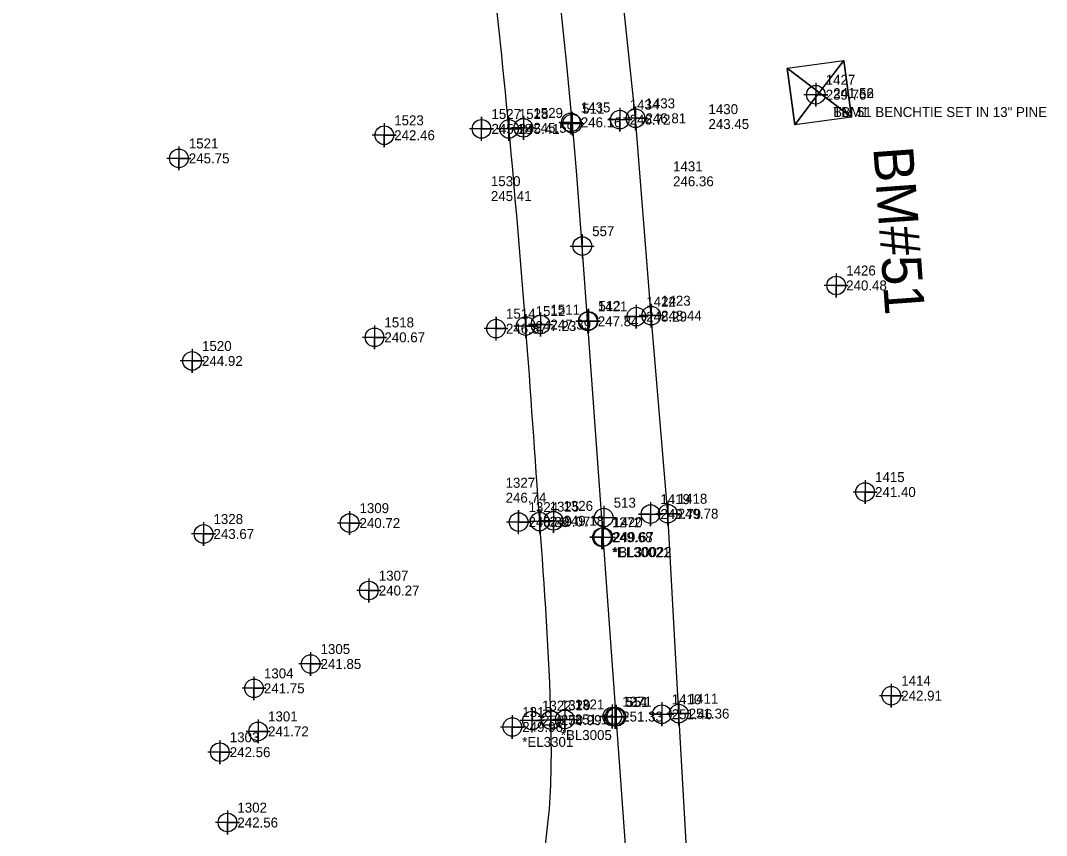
# Model space of a CAD drawing. Extents: x 2130621 to 2131998, y 642516 to 644503.
# Drawn here: x 2131091.5 to 2131349.5, y 643288.8 to 643493.6 of the extents above; entities that cross this region are included whole.
import ezdxf

# ---------------------------------------------------------------- set-up
doc = ezdxf.new("R2010")
doc.units = 0
for name, color, linetype in [('Cogo Default Point CELL', 7, 'Continuous'), ('COGO Default Point Number', 7, 'Continuous'), ('CTL Vertical Benchmark CELL', 7, 'Continuous'), ('CTL Vertical Benchmark Cogo Comment', 7, 'Continuous'), ('CTL Vertical Benchmark Cogo Elevation', 7, 'Continuous'), ('CTL Vertical Benchmark Text', 7, 'Continuous'), ('Exist Guardrail Cogo Comment', 7, 'Continuous'), ('Exist Guardrail Cogo Elevation', 7, 'Continuous'), ('Exist Guardrail Cogo Number', 7, 'Continuous'), ('Exist Guardrail Cogo Point CELL', 7, 'Continuous'), ('Exist Other Culture Fence Line Cogo Elevation', 7, 'Continuous'), ('Exist Other Culture Fence Line Cogo Number', 7, 'Continuous'), ('Exist Other Culture Fence Line Cogo Point CELL', 7, 'Continuous'), ('Exist Other Culture Sign Cogo Elevation', 7, 'Continuous'), ('Exist Other Culture Sign Cogo Number', 7, 'Continuous'), ('Exist Roads EOP', 7, 'Continuous'), ('Exist Roads EOP Cogo Elevation', 7, 'Continuous'), ('Exist Roads EOP Cogo Number', 7, 'Continuous'), ('Exist Roads EOP Cogo Point CELL', 7, 'Continuous'), ('Exist Roads EOT Cogo Comment', 7, 'Continuous'), ('Exist Roads EOT Cogo Elevation', 7, 'Continuous'), ('Exist Roads EOT Cogo Number', 7, 'Continuous'), ('Exist Roads EOT Cogo Point CELL', 7, 'Continuous'), ('Exist Roads Soil Cogo Comment', 7, 'Continuous'), ('Exist Roads Soil Cogo Elevation', 7, 'Continuous'), ('Exist Roads Soil Cogo Number', 7, 'Continuous'), ('Exist Roads Soil Cogo Point CELL', 7, 'Continuous'), ('Exist Vegetation Woods Line Cogo Elevation', 7, 'Continuous'), ('Exist Vegetation Woods Line Cogo Number', 7, 'Continuous'), ('Exist Vegetation Woods Line Cogo Point CELL', 7, 'Continuous'), ('Prop Horizontal Alignment', 7, 'Continuous')]:
    doc.layers.add(name, color=color, linetype=linetype)

msp = doc.modelspace()

# ---------------------------------------------------------------- linework, layer by layer
at = {"layer": 'Cogo Default Point CELL'}
for points in [[(2131230.23, 643470.69), (2131230.23, 643467.69)], [(2131227.23, 643467.69), (2131230.23, 643467.69)], [(2131230.23, 643467.69), (2131233.23, 643467.69)], [(2131230.23, 643467.69), (2131230.23, 643464.69)], [(2131232.75, 643439.91), (2131232.75, 643436.91)], [(2131232.75, 643439.91), (2131232.75, 643436.91)], [(2131229.75, 643436.91), (2131232.75, 643436.91)], [(2131229.75, 643436.91), (2131232.75, 643436.91)], [(2131232.75, 643436.91), (2131235.75, 643436.91)], [(2131232.75, 643436.91), (2131232.75, 643433.91)], [(2131232.75, 643436.91), (2131235.75, 643436.91)], [(2131232.75, 643436.91), (2131232.75, 643433.91)], [(2131234.31, 643421.12), (2131234.31, 643418.12)], [(2131231.31, 643418.12), (2131234.31, 643418.12)], [(2131234.31, 643418.12), (2131237.31, 643418.12)], [(2131234.31, 643418.12), (2131234.31, 643415.12)], [(2131238.16, 643371.66), (2131238.16, 643368.66)], [(2131235.16, 643368.66), (2131238.16, 643368.66)], [(2131238.16, 643368.66), (2131241.16, 643368.66)], [(2131238.16, 643368.66), (2131238.16, 643365.66)], [(2131240.95, 643321.6), (2131240.95, 643318.6)], [(2131241.32, 643321.6), (2131241.32, 643318.6)], [(2131237.95, 643318.6), (2131240.95, 643318.6)], [(2131238.32, 643318.6), (2131241.32, 643318.6)], [(2131240.95, 643318.6), (2131243.95, 643318.6)], [(2131240.95, 643318.6), (2131240.95, 643315.6)], [(2131241.32, 643318.6), (2131244.32, 643318.6)], [(2131241.32, 643318.6), (2131241.32, 643315.6)]]:
    msp.add_lwpolyline(points, dxfattribs=at)
for centre in [(2131230.23, 643467.69), (2131232.75, 643436.91), (2131232.75, 643436.91), (2131234.31, 643418.12), (2131238.16, 643368.66), (2131240.95, 643318.6), (2131241.32, 643318.6)]:
    msp.add_circle(centre, 2.34, dxfattribs=at)
at = {"layer": 'CTL Vertical Benchmark CELL'}
msp.add_line((2131292.37, 643475.49), (2131292.37, 643475.49), dxfattribs=at)
msp.add_lwpolyline([(2131298.52, 643483.58), (2131300.44, 643469.34), (2131286.19, 643467.41), (2131284.27, 643481.66)], close=True, dxfattribs=at)
for points in [[(2131300.44, 643469.34), (2131284.27, 643481.66), (2131292.35, 643475.5), (2131286.19, 643467.41), (2131298.52, 643483.58)], [(2131292.35, 643475.5), (2131300.44, 643469.34), (2131298.52, 643483.58), (2131292.35, 643475.5)], [(2131292.35, 643475.5), (2131284.27, 643481.66), (2131286.19, 643467.41), (2131292.35, 643475.5)]]:
    msp.add_lwpolyline(points, dxfattribs=at)
at = {"layer": 'Exist Guardrail Cogo Point CELL'}
msp.add_lwpolyline([(2131215.17, 643319.03), (2131215.17, 643313.03), (2131215.17, 643316.03), (2131218.17, 643316.03), (2131212.17, 643316.03)], dxfattribs=at)
msp.add_circle((2131215.17, 643316.03), 2.34, dxfattribs=at)
at = {"layer": 'Exist Other Culture Fence Line Cogo Point CELL'}
for points in [[(2131131.35, 643461.95), (2131131.35, 643455.95), (2131131.35, 643458.95), (2131134.35, 643458.95), (2131128.35, 643458.95)], [(2131134.67, 643411.04), (2131134.67, 643405.04), (2131134.67, 643408.04), (2131137.67, 643408.04), (2131131.67, 643408.04)], [(2131137.55, 643367.55), (2131137.55, 643361.55), (2131137.55, 643364.55), (2131140.55, 643364.55), (2131134.55, 643364.55)], [(2131141.64, 643312.7), (2131141.64, 643306.7), (2131141.64, 643309.7), (2131144.64, 643309.7), (2131138.64, 643309.7)], [(2131143.56, 643295.02), (2131143.56, 643289.02), (2131143.56, 643292.02), (2131146.56, 643292.02), (2131140.56, 643292.02)]]:
    msp.add_lwpolyline(points, dxfattribs=at)
for centre in [(2131131.35, 643458.95), (2131134.67, 643408.04), (2131137.55, 643364.55), (2131141.64, 643309.7), (2131143.56, 643292.02)]:
    msp.add_circle(centre, 2.34, dxfattribs=at)
at = {"layer": 'Exist Roads EOP'}
msp.add_lwpolyline([(2131264.27, 643222.56), (2131259.88, 643269.33), (2131257.02, 643319.4), (2131254.26, 643369.65), (2131250.08, 643419.42), (2131246.15, 643469.03), (2131240.84, 643519.13), (2131234.37, 643568.56), (2131226.33, 643620.18), (2131217.03, 643668.71), (2131205.62, 643717.61), (2131192.06, 643767.26), (2131177.97, 643815.09), (2131162.29, 643862.93), (2131145.36, 643910.85), (2131126.91, 643957.29), (2131112.37, 643996.12)], dxfattribs=at)
msp.add_spline([(2131166.25, 643216.7), (2131171.81, 643218.72), (2131182.37, 643223.97), (2131191.81, 643231.15), (2131200.5, 643239.7), (2131208.81, 643249.07), (2131216.07, 643259), (2131218.72, 643264.35), (2131220.54, 643270.1), (2131222.84, 643282.01), (2131224.36, 643293.92), (2131224.88, 643317.79), (2131222.06, 643367.67), (2131218.54, 643416.81), (2131214.32, 643466.35), (2131209.17, 643515.67), (2131202.79, 643565.15), (2131195.05, 643613.99), (2131186.4, 643662.48), (2131176.01, 643711.41), (2131164.62, 643759.89), (2131151.87, 643807.85), (2131137.86, 643855.41), (2131122.57, 643902.86), (2131105.96, 643949.49), (2131091.53, 643988.04)], degree=3, dxfattribs=at)
at = {"layer": 'Exist Roads EOP Cogo Point CELL'}
for points in [[(2131246.15, 643472.03), (2131246.15, 643466.03), (2131246.15, 643469.03), (2131249.15, 643469.03), (2131243.15, 643469.03)], [(2131214.32, 643469.35), (2131214.32, 643463.35), (2131214.32, 643466.35), (2131217.32, 643466.35), (2131211.32, 643466.35)], [(2131250.08, 643422.42), (2131250.08, 643416.42), (2131250.08, 643419.42), (2131253.08, 643419.42), (2131247.08, 643419.42)], [(2131218.54, 643419.81), (2131218.54, 643413.81), (2131218.54, 643416.81), (2131221.54, 643416.81), (2131215.54, 643416.81)], [(2131254.26, 643372.65), (2131254.26, 643366.65), (2131254.26, 643369.65), (2131257.26, 643369.65), (2131251.26, 643369.65)], [(2131222.06, 643370.67), (2131222.06, 643364.67), (2131222.06, 643367.67), (2131225.06, 643367.67), (2131219.06, 643367.67)], [(2131224.88, 643320.79), (2131224.88, 643314.79), (2131224.88, 643317.79), (2131227.88, 643317.79), (2131221.88, 643317.79)], [(2131257.02, 643322.4), (2131257.02, 643316.4), (2131257.02, 643319.4), (2131260.02, 643319.4), (2131254.02, 643319.4)]]:
    msp.add_lwpolyline(points, dxfattribs=at)
for centre in [(2131246.15, 643469.03), (2131214.32, 643466.35), (2131250.08, 643419.42), (2131218.54, 643416.81), (2131254.26, 643369.65), (2131222.06, 643367.67), (2131224.88, 643317.79), (2131257.02, 643319.4)]:
    msp.add_circle(centre, 2.34, dxfattribs=at)
at = {"layer": 'Exist Roads EOT Cogo Point CELL'}
for points in [[(2131217.96, 643469.63), (2131217.96, 643463.63), (2131217.96, 643466.63), (2131214.96, 643466.63), (2131220.96, 643466.63)], [(2131229.89, 643471.01), (2131229.89, 643465.01), (2131229.89, 643468.01), (2131226.89, 643468.01), (2131232.89, 643468.01)], [(2131242.19, 643471.69), (2131242.19, 643465.69), (2131242.19, 643468.69), (2131239.19, 643468.69), (2131245.19, 643468.69)], [(2131234.16, 643421), (2131234.16, 643415), (2131234.16, 643418), (2131231.16, 643418), (2131237.16, 643418)], [(2131246.35, 643422.18), (2131246.35, 643416.18), (2131246.35, 643419.18), (2131243.35, 643419.18), (2131249.35, 643419.18)], [(2131222.25, 643420.19), (2131222.25, 643414.19), (2131222.25, 643417.19), (2131219.25, 643417.19), (2131225.25, 643417.19)], [(2131249.91, 643372.55), (2131249.91, 643366.55), (2131249.91, 643369.55), (2131246.91, 643369.55), (2131252.91, 643369.55)], [(2131225.53, 643370.86), (2131225.53, 643364.86), (2131225.53, 643367.86), (2131222.53, 643367.86), (2131228.53, 643367.86)], [(2131237.7, 643366.71), (2131237.7, 643360.71), (2131237.7, 643363.71), (2131234.7, 643363.71), (2131240.7, 643363.71)], [(2131238.02, 643366.77), (2131238.02, 643360.77), (2131238.02, 643363.77), (2131235.02, 643363.77), (2131241.02, 643363.77)], [(2131228.38, 643320.94), (2131228.38, 643314.94), (2131228.38, 643317.94), (2131225.38, 643317.94), (2131231.38, 643317.94)], [(2131240.3, 643321.66), (2131240.3, 643315.66), (2131240.3, 643318.66), (2131237.3, 643318.66), (2131243.3, 643318.66)], [(2131252.75, 643322.24), (2131252.75, 643316.24), (2131252.75, 643319.24), (2131249.75, 643319.24), (2131255.75, 643319.24)]]:
    msp.add_lwpolyline(points, dxfattribs=at)
for centre in [(2131229.89, 643468.01), (2131242.19, 643468.69), (2131217.96, 643466.63), (2131246.35, 643419.18), (2131222.25, 643417.19), (2131234.16, 643418), (2131249.91, 643369.55), (2131225.53, 643367.86), (2131237.7, 643363.71), (2131238.02, 643363.77), (2131228.38, 643317.94), (2131240.3, 643318.66), (2131252.75, 643319.24)]:
    msp.add_circle(centre, 2.34, dxfattribs=at)
at = {"layer": 'Exist Roads Soil Cogo Point CELL'}
for points in [[(2131207.43, 643463.36), (2131207.43, 643469.36), (2131207.43, 643466.36), (2131210.43, 643466.36), (2131204.43, 643466.36)], [(2131211.08, 643413.16), (2131211.08, 643419.16), (2131211.08, 643416.16), (2131214.08, 643416.16), (2131208.08, 643416.16)], [(2131216.75, 643364.54), (2131216.75, 643370.54), (2131216.75, 643367.54), (2131219.75, 643367.54), (2131213.75, 643367.54)], [(2131220.14, 643314.65), (2131220.14, 643320.65), (2131220.14, 643317.65), (2131223.14, 643317.65), (2131217.14, 643317.65)], [(2131224.87, 643314.75), (2131224.87, 643320.75), (2131224.87, 643317.75), (2131227.87, 643317.75), (2131221.87, 643317.75)]]:
    msp.add_lwpolyline(points, dxfattribs=at)
for centre in [(2131207.43, 643466.36), (2131211.08, 643416.16), (2131216.75, 643367.54), (2131220.14, 643317.65), (2131224.87, 643317.75)]:
    msp.add_circle(centre, 2.34, dxfattribs=at)
at = {"layer": 'Exist Vegetation Woods Line Cogo Point CELL'}
for points in [[(2131291.47, 643477.95), (2131291.47, 643471.95), (2131291.47, 643474.95), (2131294.47, 643474.95), (2131288.47, 643474.95)], [(2131182.98, 643467.77), (2131182.98, 643461.77), (2131182.98, 643464.77), (2131185.98, 643464.77), (2131179.98, 643464.77)], [(2131296.61, 643430.01), (2131296.61, 643424.01), (2131296.61, 643427.01), (2131299.61, 643427.01), (2131293.61, 643427.01)], [(2131180.52, 643416.97), (2131180.52, 643410.97), (2131180.52, 643413.97), (2131183.52, 643413.97), (2131177.52, 643413.97)], [(2131303.87, 643378.09), (2131303.87, 643372.09), (2131303.87, 643375.09), (2131306.87, 643375.09), (2131300.87, 643375.09)], [(2131174.26, 643370.29), (2131174.26, 643364.29), (2131174.26, 643367.29), (2131177.26, 643367.29), (2131171.26, 643367.29)], [(2131179.11, 643353.33), (2131179.11, 643347.33), (2131179.11, 643350.33), (2131182.11, 643350.33), (2131176.11, 643350.33)], [(2131164.47, 643334.87), (2131164.47, 643328.87), (2131164.47, 643331.87), (2131167.47, 643331.87), (2131161.47, 643331.87)], [(2131150.23, 643328.75), (2131150.23, 643322.75), (2131150.23, 643325.75), (2131153.23, 643325.75), (2131147.23, 643325.75)], [(2131310.45, 643326.9), (2131310.45, 643320.9), (2131310.45, 643323.9), (2131313.45, 643323.9), (2131307.45, 643323.9)], [(2131151.27, 643317.93), (2131151.27, 643311.93), (2131151.27, 643314.93), (2131154.27, 643314.93), (2131148.27, 643314.93)]]:
    msp.add_lwpolyline(points, dxfattribs=at)
for centre in [(2131291.47, 643474.95), (2131182.98, 643464.77), (2131296.61, 643427.01), (2131180.52, 643413.97), (2131303.87, 643375.09), (2131174.26, 643367.29), (2131179.11, 643350.33), (2131164.47, 643331.87), (2131150.23, 643325.75), (2131310.45, 643323.9), (2131151.27, 643314.93)]:
    msp.add_circle(centre, 2.34, dxfattribs=at)
at = {"layer": 'Prop Horizontal Alignment'}
msp.add_line((2131251.47, 643178.51), (2131232.75, 643436.91), dxfattribs=at)
msp.add_arc((2129448.47, 643307.66), 1788.96, 4.14306, 22.49968, dxfattribs=at)

# ---------------------------------------------------------------- texts
at = {"layer": 'COGO Default Point Number'}
for s, p in [('511', (2131232.73, 643470.19)), ('557', (2131235.25, 643439.41)), ('512', (2131236.81, 643420.62)), ('513', (2131240.66, 643371.16)), ('514', (2131243.45, 643321.1)), ('551', (2131243.82, 643321.1))]:
    msp.add_text(s, height=2.5, dxfattribs=at).set_placement(p)
at = {"layer": 'CTL Vertical Benchmark Cogo Comment'}
for s in ['TBM1', 'BM 51 BENCHTIE SET IN 13" PINE']:
    msp.add_text(s, height=2.5, dxfattribs=at).set_placement((2131295.85, 643469.35))
at = {"layer": 'CTL Vertical Benchmark Cogo Elevation'}
for s in ['241.56', '241.52']:
    msp.add_text(s, height=2.5, dxfattribs=at).set_placement((2131295.85, 643474.1))
at = {"layer": 'CTL Vertical Benchmark Text'}
msp.add_text('BM#51   ', height=10, rotation=274.1431, dxfattribs=at).set_placement((2131305.92, 643461.61))
at = {"layer": 'Exist Guardrail Cogo Comment'}
msp.add_text('*EL3301', height=2.5, dxfattribs=at).set_placement((2131217.67, 643311.03))
at = {"layer": 'Exist Guardrail Cogo Elevation'}
msp.add_text('249.96', height=2.5, dxfattribs=at).set_placement((2131217.67, 643314.78))
at = {"layer": 'Exist Guardrail Cogo Number'}
msp.add_text('1318', height=2.5, dxfattribs=at).set_placement((2131217.67, 643318.53))
at = {"layer": 'Exist Other Culture Fence Line Cogo Elevation'}
for s, p in [('245.75', (2131133.85, 643457.7)), ('244.92', (2131137.17, 643406.79)), ('243.67', (2131140.05, 643363.3)), ('242.56', (2131144.14, 643308.45)), ('242.56', (2131146.06, 643290.77))]:
    msp.add_text(s, height=2.5, dxfattribs=at).set_placement(p)
at = {"layer": 'Exist Other Culture Fence Line Cogo Number'}
for s, p in [('1521', (2131133.85, 643461.45)), ('1520', (2131137.17, 643410.54)), ('1328', (2131140.05, 643367.05)), ('1303', (2131144.14, 643312.2)), ('1302', (2131146.06, 643294.52))]:
    msp.add_text(s, height=2.5, dxfattribs=at).set_placement(p)
at = {"layer": 'Exist Other Culture Sign Cogo Elevation'}
for s, p in [('243.45', (2131264.49, 643466.32)), ('246.36', (2131255.59, 643451.94)), ('245.41', (2131209.79, 643448.22)), ('246.74', (2131213.49, 643372.41))]:
    msp.add_text(s, height=2.5, dxfattribs=at).set_placement(p)
at = {"layer": 'Exist Other Culture Sign Cogo Number'}
for s, p in [('1430', (2131264.49, 643470.07)), ('1431', (2131255.59, 643455.69)), ('1530', (2131209.79, 643451.97)), ('1327', (2131213.49, 643376.16))]:
    msp.add_text(s, height=2.5, dxfattribs=at).set_placement(p)
at = {"layer": 'Exist Roads EOP Cogo Elevation'}
for s, p in [('246.81', (2131248.65, 643467.78)), ('245.41', (2131216.82, 643465.1)), ('248.44', (2131252.58, 643418.17)), ('247.23', (2131221.04, 643415.56)), ('249.07', (2131224.56, 643366.42)), ('249.78', (2131256.76, 643368.4)), ('251.36', (2131259.52, 643318.15)), ('250.99', (2131227.38, 643316.54))]:
    msp.add_text(s, height=2.5, dxfattribs=at).set_placement(p)
at = {"layer": 'Exist Roads EOP Cogo Number'}
for s, p in [('1433', (2131248.65, 643471.53)), ('1528', (2131216.82, 643468.85)), ('1423', (2131252.58, 643421.92)), ('1512', (2131221.04, 643419.31)), ('1418', (2131256.76, 643372.15)), ('1325', (2131224.56, 643370.17)), ('1319', (2131227.38, 643320.29)), ('1411', (2131259.52, 643321.9))]:
    msp.add_text(s, height=2.5, dxfattribs=at).set_placement(p)
at = {"layer": 'Exist Roads EOT Cogo Comment'}
for s, p in [('*EL30021', (2131240.2, 643358.71)), ('*BL30022', (2131240.52, 643358.77))]:
    msp.add_text(s, height=2.5, dxfattribs=at).set_placement(p)
at = {"layer": 'Exist Roads EOT Cogo Elevation'}
for s, p in [('246.72', (2131244.69, 643467.44)), ('245.59', (2131220.46, 643465.38)), ('246.16', (2131232.39, 643466.76)), ('247.39', (2131224.75, 643415.94)), ('247.84', (2131236.66, 643416.75)), ('248.29', (2131248.85, 643417.93)), ('249.18', (2131228.03, 643366.61)), ('249.79', (2131252.41, 643368.3)), ('249.68', (2131240.2, 643362.46)), ('249.67', (2131240.52, 643362.52)), ('251.46', (2131255.25, 643317.99)), ('251.11', (2131230.88, 643316.69)), ('251.33', (2131242.8, 643317.41))]:
    msp.add_text(s, height=2.5, dxfattribs=at).set_placement(p)
at = {"layer": 'Exist Roads EOT Cogo Number'}
for s, p in [('1435', (2131232.39, 643470.51)), ('1434', (2131244.69, 643471.19)), ('1529', (2131220.46, 643469.13)), ('1422', (2131248.85, 643421.68)), ('1511', (2131224.75, 643419.69)), ('1421', (2131236.66, 643420.5)), ('1419', (2131252.41, 643372.05)), ('1326', (2131228.03, 643370.36)), ('1272', (2131240.2, 643366.21)), ('1420', (2131240.52, 643366.27)), ('1321', (2131230.88, 643320.44)), ('1271', (2131242.8, 643321.16)), ('1410', (2131255.25, 643321.74))]:
    msp.add_text(s, height=2.5, dxfattribs=at).set_placement(p)
at = {"layer": 'Exist Roads Soil Cogo Comment'}
msp.add_text('*BL3005', height=2.5, dxfattribs=at).set_placement((2131227.37, 643312.75))
at = {"layer": 'Exist Roads Soil Cogo Elevation'}
for s, p in [('245.18', (2131209.93, 643465.11)), ('246.87', (2131213.58, 643414.91)), ('248.89', (2131219.25, 643366.29)), ('250.74', (2131222.64, 643316.4)), ('250.99', (2131227.37, 643316.5))]:
    msp.add_text(s, height=2.5, dxfattribs=at).set_placement(p)
at = {"layer": 'Exist Roads Soil Cogo Number'}
for s, p in [('1527', (2131209.93, 643468.86)), ('1514', (2131213.58, 643418.66)), ('1324', (2131219.25, 643370.04)), ('1322', (2131222.64, 643320.15)), ('1320', (2131227.37, 643320.25))]:
    msp.add_text(s, height=2.5, dxfattribs=at).set_placement(p)
at = {"layer": 'Exist Vegetation Woods Line Cogo Elevation'}
for s, p in [('239.76', (2131293.97, 643473.7)), ('242.46', (2131185.48, 643463.52)), ('240.48', (2131299.11, 643425.76)), ('240.67', (2131183.02, 643412.72)), ('241.40', (2131306.37, 643373.84)), ('240.72', (2131176.76, 643366.04)), ('240.27', (2131181.61, 643349.08)), ('241.85', (2131166.97, 643330.62)), ('241.75', (2131152.73, 643324.5)), ('242.91', (2131312.95, 643322.65)), ('241.72', (2131153.77, 643313.68))]:
    msp.add_text(s, height=2.5, dxfattribs=at).set_placement(p)
at = {"layer": 'Exist Vegetation Woods Line Cogo Number'}
for s, p in [('1427', (2131293.97, 643477.45)), ('1523', (2131185.48, 643467.27)), ('1426', (2131299.11, 643429.51)), ('1518', (2131183.02, 643416.47)), ('1415', (2131306.37, 643377.59)), ('1309', (2131176.76, 643369.79)), ('1307', (2131181.61, 643352.83)), ('1305', (2131166.97, 643334.37)), ('1304', (2131152.73, 643328.25)), ('1414', (2131312.95, 643326.4)), ('1301', (2131153.77, 643317.43))]:
    msp.add_text(s, height=2.5, dxfattribs=at).set_placement(p)

doc.saveas('drawing.dxf')
